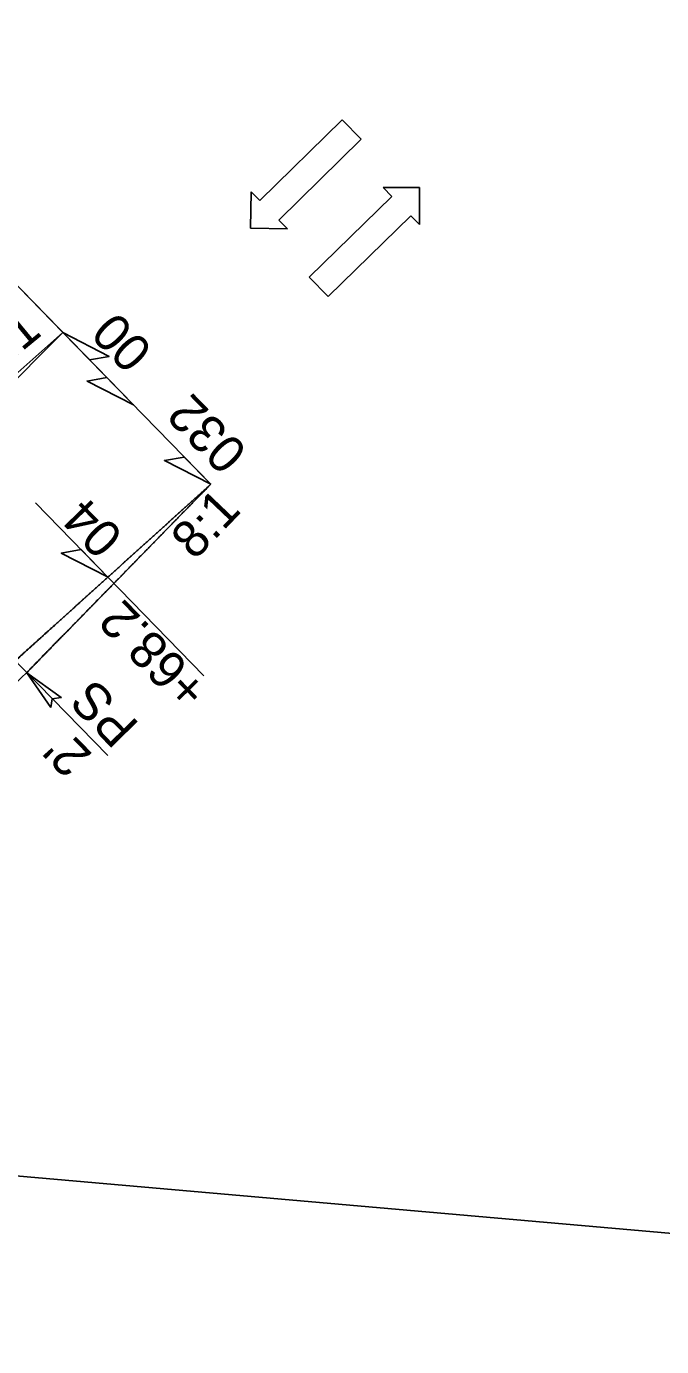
# Model space of a CAD drawing. Extents: x 1183930 to 1185370, y 573068 to 574871.
# Drawn here: x 1184882.5 to 1184959.5, y 574393 to 574553.1 of the extents above; entities that cross this region are included whole.
import ezdxf

# ---------------------------------------------------------------- set-up
doc = ezdxf.new("R2010")
doc.units = 0
for name, color, linetype in [('E_NCDOT_Vertical_Profile_Ground_Line', 7, 'Continuous'), ('P_NCDOT_Horizontal_Alignment', 7, 'Continuous'), ('PC_BEAM', 7, 'Continuous'), ('PC_COLUMN', 7, 'Continuous'), ('PC_OBJECT', 7, 'Continuous'), ('PC_PADFOOTING', 7, 'Continuous'), ('PC_SLAB', 7, 'Continuous'), ('PS_HATCH', 7, 'Continuous')]:
    doc.layers.add(name, color=color, linetype=linetype)

msp = doc.modelspace()

# ---------------------------------------------------------------- linework, layer by layer
msp.add_lwpolyline([(1184885.47, 574470.48), (1184882.55, 574474.7), (1184886.75, 574471.7), (1184885.66, 574471.53)], close=True)
at = {"layer": 'E_NCDOT_Vertical_Profile_Ground_Line'}
for p, q in [((1184867.9, 574499.11), (1184886.93, 574515.99)), ((1184867.9, 574499.11), (1184886.93, 574515.99)), ((1184887.12, 574479.4), (1184904.87, 574497.57)), ((1184887.12, 574479.4), (1184904.87, 574497.57))]:
    msp.add_line(p, q, dxfattribs=at)
for points in [[(1184882.55, 574474.7), (1184882.62, 574474.78), (1184882.77, 574474.94), (1184883, 574475.17), (1184883.23, 574475.41), (1184883.46, 574475.64), (1184883.69, 574475.88), (1184883.92, 574476.12), (1184884.14, 574476.35), (1184884.37, 574476.59), (1184884.6, 574476.82), (1184884.83, 574477.06), (1184885.06, 574477.29), (1184885.29, 574477.53), (1184885.52, 574477.76), (1184885.74, 574478), (1184885.97, 574478.23), (1184886.2, 574478.46), (1184886.43, 574478.7), (1184886.66, 574478.93), (1184886.89, 574479.17), (1184887.04, 574479.33), (1184887.12, 574479.4)], [(1184882.55, 574474.7), (1184882.62, 574474.78), (1184882.77, 574474.94), (1184883, 574475.17), (1184883.23, 574475.41), (1184883.46, 574475.64), (1184883.69, 574475.88), (1184883.92, 574476.12), (1184884.14, 574476.35), (1184884.37, 574476.59), (1184884.6, 574476.82), (1184884.83, 574477.06), (1184885.06, 574477.29), (1184885.29, 574477.53), (1184885.52, 574477.76), (1184885.74, 574478), (1184885.97, 574478.23), (1184886.2, 574478.46), (1184886.43, 574478.7), (1184886.66, 574478.93), (1184886.89, 574479.17), (1184887.04, 574479.33), (1184887.12, 574479.4)], [(1184882.52, 574474.68), (1184882.52, 574474.68), (1184882.53, 574474.69), (1184882.54, 574474.7), (1184882.55, 574474.7)], [(1184882.52, 574474.68), (1184882.52, 574474.68), (1184882.53, 574474.69), (1184882.54, 574474.7), (1184882.55, 574474.7)]]:
    msp.add_open_spline(points, degree=3, dxfattribs=at)
at = {"layer": 'P_NCDOT_Horizontal_Alignment'}
for p, q in [((1184869.02, 574497.99), (1184886.93, 574515.99)), ((1184869.02, 574497.99), (1184886.93, 574515.99)), ((1184886.93, 574515.99), (1184904.87, 574497.57)), ((1184886.01, 574480.54), (1184904.87, 574497.57)), ((1184886.01, 574480.54), (1184904.87, 574497.57))]:
    msp.add_line(p, q, dxfattribs=at)
msp.add_open_spline([(1184881.14, 574476.13), (1184881.23, 574476.2), (1184881.39, 574476.35), (1184881.63, 574476.57), (1184881.87, 574476.79), (1184882.12, 574477.01), (1184882.36, 574477.24), (1184882.6, 574477.46), (1184882.85, 574477.68), (1184883.09, 574477.9), (1184883.33, 574478.12), (1184883.58, 574478.34), (1184883.82, 574478.56), (1184884.06, 574478.78), (1184884.31, 574479), (1184884.55, 574479.22), (1184884.79, 574479.44), (1184885.04, 574479.66), (1184885.28, 574479.88), (1184885.52, 574480.1), (1184885.77, 574480.32), (1184885.93, 574480.47), (1184886.01, 574480.54)], degree=3, dxfattribs=at)
msp.add_open_spline([(1184881.14, 574476.13), (1184881.23, 574476.2), (1184881.39, 574476.35), (1184881.63, 574476.57), (1184881.87, 574476.79), (1184882.12, 574477.01), (1184882.36, 574477.24), (1184882.6, 574477.46), (1184882.85, 574477.68), (1184883.09, 574477.9), (1184883.33, 574478.12), (1184883.58, 574478.34), (1184883.82, 574478.56), (1184884.06, 574478.78), (1184884.31, 574479), (1184884.55, 574479.22), (1184884.79, 574479.44), (1184885.04, 574479.66), (1184885.28, 574479.88), (1184885.52, 574480.1), (1184885.77, 574480.32), (1184885.93, 574480.47), (1184886.01, 574480.54)], degree=3, dxfattribs=at)
at = {"layer": 'PC_BEAM'}
for p, q in [((1184920.81, 574541.78), (1184910.81, 574531.98)), ((1184923.12, 574539.42), (1184920.81, 574541.78)), ((1184913.12, 574529.62), (1184923.12, 574539.42)), ((1184909.76, 574533.05), (1184909.68, 574528.63)), ((1184910.81, 574531.98), (1184909.76, 574533.05)), ((1184926.82, 574532.5), (1184925.77, 574533.57)), ((1184925.77, 574533.57), (1184930.19, 574533.56)), ((1184930.19, 574533.56), (1184930.18, 574529.07)), ((1184916.82, 574522.7), (1184926.82, 574532.5)), ((1184929.13, 574530.14), (1184919.13, 574520.34)), ((1184930.18, 574529.07), (1184929.13, 574530.14)), ((1184909.68, 574528.63), (1184914.17, 574528.55)), ((1184914.17, 574528.55), (1184913.12, 574529.62)), ((1184919.13, 574520.34), (1184916.82, 574522.7))]:
    msp.add_line(p, q, dxfattribs=at)
at = {"layer": 'PC_COLUMN'}
for points in [[(1184886.93, 574515.99), (1184892.55, 574513.09), (1184890.16, 574512.68)], [(1184895.5, 574507.19), (1184889.88, 574510.1), (1184892.27, 574510.51)], [(1184904.87, 574497.57), (1184899.25, 574500.47), (1184901.64, 574500.88)], [(1184892.37, 574486.33), (1184886.75, 574489.23), (1184889.14, 574489.64)]]:
    msp.add_lwpolyline(points, close=True, dxfattribs=at)
at = {"layer": 'PC_OBJECT'}
msp.add_arc((1186063.32, 573271.23), 1686, 134.45454, 135.37366, dxfattribs=at)
for points in [[(1184904.87, 574497.57), (1184904.23, 574496.99), (1184903.9, 574496.7), (1184903.58, 574496.41), (1184903.26, 574496.12), (1184902.94, 574495.83), (1184902.62, 574495.54), (1184902.3, 574495.25), (1184901.98, 574494.96), (1184901.66, 574494.67), (1184901.34, 574494.38), (1184901.01, 574494.09), (1184900.69, 574493.8), (1184900.37, 574493.51), (1184900.05, 574493.22), (1184899.73, 574492.93), (1184899.41, 574492.64), (1184899.09, 574492.35), (1184898.77, 574492.06), (1184898.44, 574491.77), (1184898.12, 574491.48), (1184897.8, 574491.19), (1184897.48, 574490.9), (1184897.16, 574490.61), (1184896.96, 574490.43)], [(1184897.42, 574489.95), (1184897.61, 574490.14), (1184897.92, 574490.45), (1184898.22, 574490.76), (1184898.52, 574491.07), (1184898.82, 574491.38), (1184899.12, 574491.69), (1184899.43, 574492), (1184899.73, 574492.31), (1184900.03, 574492.62), (1184900.33, 574492.93), (1184900.64, 574493.24), (1184900.94, 574493.55), (1184901.24, 574493.86), (1184901.54, 574494.17), (1184901.85, 574494.48), (1184902.15, 574494.79), (1184902.45, 574495.09), (1184902.75, 574495.4), (1184903.05, 574495.71), (1184903.36, 574496.02), (1184903.66, 574496.33), (1184903.96, 574496.64), (1184904.26, 574496.95), (1184904.87, 574497.57)], [(1184896.96, 574490.43), (1184896.84, 574490.32), (1184896.52, 574490.03), (1184896.2, 574489.74), (1184895.88, 574489.45), (1184895.55, 574489.16), (1184895.23, 574488.87), (1184894.91, 574488.58), (1184894.59, 574488.29), (1184894.27, 574488), (1184893.95, 574487.71), (1184893.63, 574487.42), (1184893.31, 574487.13), (1184892.99, 574486.84), (1184892.66, 574486.55), (1184892.34, 574486.26), (1184892.02, 574485.97), (1184891.7, 574485.68), (1184891.38, 574485.39), (1184891.06, 574485.1), (1184890.74, 574484.81), (1184890.42, 574484.52), (1184890.09, 574484.23), (1184889.77, 574483.94), (1184889.45, 574483.65), (1184889.13, 574483.36), (1184889.05, 574483.28)], [(1184889.98, 574482.33), (1184890.06, 574482.41), (1184890.36, 574482.72), (1184890.66, 574483.03), (1184890.96, 574483.34), (1184891.26, 574483.65), (1184891.57, 574483.96), (1184891.87, 574484.27), (1184892.17, 574484.58), (1184892.47, 574484.88), (1184892.78, 574485.19), (1184893.08, 574485.5), (1184893.38, 574485.81), (1184893.68, 574486.12), (1184893.99, 574486.43), (1184894.29, 574486.74), (1184894.59, 574487.05), (1184894.89, 574487.36), (1184895.19, 574487.67), (1184895.5, 574487.98), (1184895.8, 574488.29), (1184896.1, 574488.6), (1184896.4, 574488.91), (1184896.71, 574489.22), (1184897.01, 574489.53), (1184897.31, 574489.83), (1184897.42, 574489.95)], [(1184889.05, 574483.28), (1184888.81, 574483.07), (1184888.49, 574482.78), (1184888.17, 574482.49), (1184887.85, 574482.2), (1184887.53, 574481.91), (1184887.2, 574481.62), (1184886.88, 574481.33), (1184886.56, 574481.04), (1184886.24, 574480.75), (1184885.92, 574480.46), (1184885.6, 574480.17), (1184885.28, 574479.88), (1184884.96, 574479.59), (1184884.65, 574479.31), (1184884.33, 574479.02), (1184884.01, 574478.73), (1184883.69, 574478.44), (1184883.37, 574478.15), (1184883.05, 574477.86), (1184882.74, 574477.58), (1184882.42, 574477.29), (1184882.1, 574477), (1184881.78, 574476.71), (1184881.46, 574476.42), (1184881.14, 574476.13)], [(1184882.55, 574474.7), (1184882.84, 574475.01), (1184883.14, 574475.32), (1184883.44, 574475.63), (1184883.74, 574475.93), (1184884.04, 574476.24), (1184884.34, 574476.55), (1184884.64, 574476.86), (1184884.94, 574477.17), (1184885.24, 574477.47), (1184885.54, 574477.78), (1184885.83, 574478.09), (1184886.13, 574478.39), (1184886.43, 574478.7), (1184886.73, 574479.01), (1184887.03, 574479.32), (1184887.33, 574479.62), (1184887.64, 574479.93), (1184887.94, 574480.24), (1184888.24, 574480.55), (1184888.54, 574480.86), (1184888.85, 574481.17), (1184889.15, 574481.48), (1184889.45, 574481.79), (1184889.75, 574482.1), (1184889.98, 574482.33)]]:
    msp.add_spline(points, degree=3, dxfattribs=at)
at = {"layer": 'PC_PADFOOTING'}
for p, q in [((1184886.93, 574515.99), (1184857.46, 574546.27)), ((1184904.04, 574474.35), (1184892.4, 574486.31)), ((1184876.37, 574481), (1184892.4, 574464.66)), ((1184855.59, 574415.91), (1185117.2, 574392.96))]:
    msp.add_line(p, q, dxfattribs=at)
at = {"layer": 'PC_SLAB'}
msp.add_line((1184883.62, 574495.31), (1184892.39, 574486.3), dxfattribs=at)
at = {"layer": 'PS_HATCH'}
msp.add_line((1184760.25, 574646.12), (1184895.5, 574507.19), dxfattribs=at)

# ---------------------------------------------------------------- texts
at = {"layer": 'PC_PADFOOTING'}
for s, rotation, p in [('8:1', 39.532, (1184878.09, 574510.43)), ('8:1', 46.3953, (1184902.93, 574488.24)), ('+68.2', 134.2318, (1184904.84, 574472.91)), ('PS', 134.4545, (1184896.35, 574468.43)), ("2'", 134.4545, (1184890.65, 574464.78))]:
    msp.add_text(s, height=4.5, rotation=rotation, dxfattribs=at).set_placement(p)
at = {"layer": 'PC_SLAB'}
for s, p in [('00', (1184898.02, 574513.94)), ('032', (1184909.52, 574501.63)), ('04', (1184894.46, 574491.4))]:
    msp.add_text(s, height=4.5, rotation=134.2318, dxfattribs=at).set_placement(p)

doc.saveas('drawing.dxf')
